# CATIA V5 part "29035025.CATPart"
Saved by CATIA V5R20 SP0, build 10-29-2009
Part number: 29035025
Definition: NONE
Nomenclature: 29035025
Source: Unknown
Description: 29035025
Bounding box of the stored display mesh (mm): x -12.5 to 44.548, y -31.5 to 66.048, z -21.5 to 21.5
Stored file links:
  C:\Users\Utente\Desktop\IO LAVORO\3D X SITO CF\X SITO\PLASTICA\RF1\29035025.CATPart
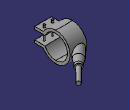
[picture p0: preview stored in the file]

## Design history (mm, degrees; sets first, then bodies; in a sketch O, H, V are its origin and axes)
Body1 "29035025" (main body)
  Solid1: solid without history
